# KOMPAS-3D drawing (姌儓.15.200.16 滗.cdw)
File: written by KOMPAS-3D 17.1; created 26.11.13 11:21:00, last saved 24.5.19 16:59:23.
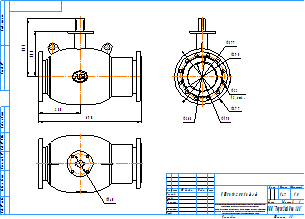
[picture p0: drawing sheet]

Sheet 1: A3, landscape

Title block, sheet 1: name: КШГИ.15.200.16 ф/ф; material: Сталь 20  ГОСТ 1050-2013; mass: 147; sheets: 1; organisation: ООО "Торговый дом АДЛ"; sheet format: A3; stored path: C:\Users\kka\Desktop\Альбом БИВАЛ\1 Ду150 Полнопроходной сварка-сварка на опоре с приводом SG12.1\КШТ 14.150.25 СС + SG12.1 альбом стр.1.cdw

Views: Спереди 2, Проекционный вид 3, Проекционный вид 4
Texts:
  Klimkovich
  ADL
  K5LT_THIN_RGB_0_0_0_THICK_0.18
  K5LT_AXLED_RGB_255_128_0_SC_1_THICK_0.18
  Рама для чертежей
  Лит-Масса-Масштаб
  Материал-Предприятие
  Масштаб
  Изм.
  Лист
  № докум.
  Подп.
  Дата
  Лит.
  Разраб.
  Пров.
  Т.контр.
  Листов
  Внимание! Данный продукт является объектом авторского права ООО «Торговый Дом АДЛ».
  Запрещается изменение, копирование, распространение
  (в том числе путем копирования на другие сайты и ресурсы в Интернете)
  или любое иное использование информации и объектов без предварительного
  согласия правообладателя (ООО «Торговый Дом АДЛ»).
  Н.контр.
  Утв.
  Изменение
  Номер документа
  Подпись
  Обозначение документа
  Наименование изделия
  Масса изделия по ГОСТ 2.109-73
  Порядковый номер листа
  Общее количество листов в документе
  Характер работы, выполненной лицом, подписавшим документ
  Наименование или индекс предприятия, выпускающего документ
  Инв. № подл.
  Подп. и дата
  Взам. инв. №
  Инв. № дубл.
  Инвентарный номер подлинника по ГОСТ 2.501-68
  Подпись принявшего подлинник в отдел технической документации
  Инвентарный номер подлинника, взамен которого выпущен данный подлинник
  Инвентарный номер дубликата по ГОСТ 2.502-68
  Подпись принявшего дубликат в отдел технической документации
  Справ. №
  Перв. примен.
  Обозначение документа, взамен или на основании которого выпущен данный документ
  Обозначение документа, в котором впервые записан данный документ
  Подпись лица, копировавшего чертеж
  Обозначение формата листа
  !Рама для чертежа
Dimensions and other numbers on the sheet: 280; 306; 389; 690; 140; 377; 295; 268; 22; 12 отв.; 195; 1:5; 1; 147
